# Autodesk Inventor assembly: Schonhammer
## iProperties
Created: 2005-12
Part Number: Schonhammer
Document SubType Name: Assembly
Designer: Kumpf
Manufacturer: Standard
Standards Organization: Custom
Author: Kumpf
